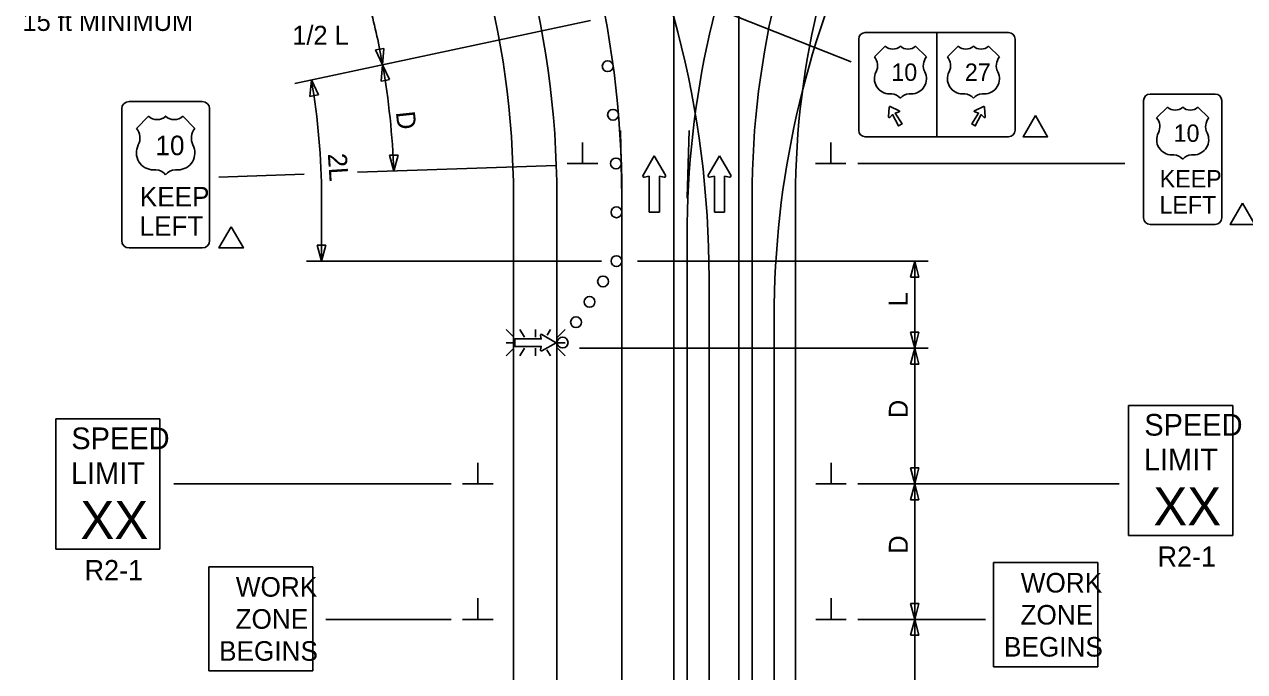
# Model space of a CAD drawing. Extents: x 16440 to 18464, y 5737 to 6974.
# Drawn here: x 16741.1 to 17191.2, y 6394.6 to 6633.2 of the extents above; entities that cross this region are included whole.
import ezdxf

# ---------------------------------------------------------------- set-up
doc = ezdxf.new("R2010")
doc.units = 0
for name, color, linetype in [('ALI_LEGAL_EX', 7, 'Continuous'), ('MT_SCRATCH_LEVEL_E', 7, 'Continuous'), ('PAVT_EDGE_EX', 7, 'Continuous'), ('TRAFFIC_SIGNS_PR', 7, 'Continuous'), ('TYPICAL_EX', 7, 'Continuous'), ('TYPICAL_TEXT_DIMEN_PR', 7, 'Continuous')]:
    doc.layers.add(name, color=color, linetype=linetype)

msp = doc.modelspace()

# ---------------------------------------------------------------- linework, layer by layer
at = {"layer": 'ALI_LEGAL_EX'}
for p, q in [((16980.68, 6974.12), (16980.68, 6155.98)), ((17004.68, 6974.12), (17004.68, 6155.98)), ((16980.68, 6891.53), (16980.68, 6027.61)), ((17004.68, 6891.53), (17004.68, 6027.61)), ((16961.51, 6069.17), (16961.51, 6569.52)), ((16985.51, 6054.68), (16985.51, 6555.03)), ((16993.65, 6039.29), (16993.65, 6539.64)), ((17017.65, 6024.8), (17017.65, 6525.15))]:
    msp.add_line(p, q, dxfattribs=at)
for points in [[(16961.46, 6569.17), (16961.51, 6569.52), (16960.94, 6594.16)], [(16985.56, 6569.17), (16985.51, 6569.52), (16986.34, 6594.15)], [(16961.51, 6469.17), (16961.51, 6494.17)], [(16985.51, 6469.17), (16985.51, 6494.17)]]:
    msp.add_lwpolyline(points, dxfattribs=at)
for centre, radius, start, end in [((16597.51, 6569.52), 364, 0, 57.2958), ((16629.65, 6539.64), 364, 0, 57.2958), ((17325.51, 6555.03), 340, 129.5666, 180), ((17357.65, 6525.15), 340, 129.5666, 180)]:
    msp.add_arc(centre, radius, start, end, dxfattribs=at)
at = {"layer": 'MT_SCRATCH_LEVEL_E'}
for p, q in [((16973.43, 6584.82), (16969.32, 6577.59)), ((16977.58, 6577.59), (16973.43, 6584.82)), ((16997.48, 6584.82), (16993.37, 6577.59)), ((17001.63, 6577.59), (16997.48, 6584.82)), ((16969.8, 6576.9), (16971.58, 6577.22)), ((16971.58, 6577.22), (16971.58, 6563.96)), ((16975.32, 6563.96), (16975.32, 6577.22)), ((16975.32, 6577.22), (16977.1, 6576.9)), ((16993.85, 6576.9), (16995.63, 6577.22)), ((16995.63, 6577.22), (16995.63, 6563.96)), ((16999.37, 6563.96), (16999.37, 6577.22)), ((16999.37, 6577.22), (17001.15, 6576.9)), ((16971.58, 6563.96), (16975.32, 6563.96)), ((16995.63, 6563.96), (16999.37, 6563.96))]:
    msp.add_line(p, q, dxfattribs=at)
for centre, start, end in [((16969.73, 6577.36), 150.4248, 279.9638), ((16977.17, 6577.36), 260.0362, 29.7731), ((16993.78, 6577.36), 150.4248, 279.9638), ((17001.22, 6577.36), 260.0362, 29.7731)]:
    msp.add_arc(centre, 0.463, start, end, dxfattribs=at)
at = {"layer": 'PAVT_EDGE_EX'}
for p, q in [((16921.51, 6569.52), (16921.51, 6043.9)), ((16937.51, 6569.52), (16937.51, 6043.9)), ((17009.51, 6569.52), (17009.51, 6043.9)), ((17025.51, 6569.52), (17025.51, 6043.9))]:
    msp.add_line(p, q, dxfattribs=at)
for centre, radius, start, end in [((16597.51, 6569.52), 340, 0, 62.1564), ((16597.51, 6569.52), 324, 0, 62.1564), ((17325.51, 6569.52), 316, 123.7854, 180), ((17325.51, 6569.52), 300, 123.7854, 180), ((17325.51, 6569.52), 300, 180, 180.00000277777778)]:
    msp.add_arc(centre, radius, start, end, dxfattribs=at)
at = {"layer": 'TRAFFIC_SIGNS_PR'}
for p, q in [((17051.26, 6630.24), (17104.13, 6630.24)), ((17077.7, 6630.24), (17077.7, 6591.79)), ((17048.86, 6627.84), (17048.86, 6594.19)), ((17106.53, 6627.84), (17106.53, 6594.19)), ((17180.37, 6607.57), (17156.34, 6607.57)), ((16806.71, 6604.81), (16779.71, 6604.81)), ((17059.85, 6599.15), (17060.14, 6602.78)), ((17060.51, 6602.99), (17063.79, 6601.42)), ((17094.88, 6602.99), (17091.6, 6601.42)), ((17095.54, 6599.15), (17095.25, 6602.78)), ((17153.94, 6605.16), (17153.94, 6561.91)), ((17182.77, 6561.91), (17182.77, 6605.16)), ((16777.01, 6602.11), (16777.01, 6553.51)), ((16809.41, 6553.51), (16809.41, 6602.11)), ((17051.26, 6591.79), (17104.13, 6591.79)), ((17156.34, 6559.51), (17180.37, 6559.51)), ((16779.71, 6550.81), (16806.71, 6550.81)), ((16921.58, 6517.92), (16918.76, 6520.74)), ((16923.88, 6520.74), (16925.51, 6517.92)), ((16929.67, 6517.92), (16929.67, 6520.74)), ((16935.13, 6520.74), (16933.93, 6518.65)), ((16940.57, 6520.74), (16937.75, 6517.92)), ((16921.58, 6515.89), (16918.76, 6515.89)), ((16921.58, 6513.86), (16918.76, 6511.04)), ((16925.53, 6513.86), (16923.9, 6511.04)), ((16929.67, 6513.86), (16929.67, 6511.04)), ((16933.85, 6513.23), (16935.11, 6511.04)), ((16937.75, 6515.89), (16940.57, 6515.89)), ((16940.57, 6511.04), (16937.75, 6513.86)), ((17148.4, 6492.75), (17186.8, 6492.75)), ((17148.4, 6444.75), (17148.4, 6492.75)), ((17186.8, 6444.75), (17186.8, 6492.75)), ((16752.64, 6487.76), (16791.04, 6487.76)), ((16752.64, 6439.76), (16752.64, 6487.76)), ((16791.04, 6439.76), (16791.04, 6487.76)), ((17148.4, 6444.75), (17186.8, 6444.75)), ((16752.64, 6439.76), (16791.04, 6439.76)), ((16809.1, 6394.86), (16809.1, 6433.26)), ((16809.1, 6433.26), (16847.5, 6433.26)), ((16847.5, 6394.86), (16847.5, 6433.26)), ((17098.62, 6396.4), (17098.62, 6434.8)), ((17098.62, 6434.8), (17137.02, 6434.8)), ((17137.02, 6396.4), (17137.02, 6434.8)), ((17098.62, 6396.4), (17137.02, 6396.4)), ((16809.1, 6394.86), (16847.5, 6394.86))]:
    msp.add_line(p, q, dxfattribs=at)
for points in [[(17063.75, 6600.94), (17062.34, 6600.55), (17064.86, 6596.56), (17063.53, 6595.8), (17061.33, 6599.97), (17060.29, 6598.94)], [(17091.64, 6600.94), (17093.05, 6600.55), (17090.53, 6596.56), (17091.86, 6595.8), (17094.06, 6599.97), (17095.1, 6598.94)], [(16931.49, 6518.57), (16931.72, 6517.28), (16922, 6517.28), (16922, 6514.53), (16931.72, 6514.53), (16931.49, 6513.23)], [(16931.99, 6512.88), (16937.3, 6515.89), (16931.99, 6518.93)]]:
    msp.add_lwpolyline(points, dxfattribs=at)
for centre in [(16956.26, 6617.81), (16958.22, 6599.92), (16959.28, 6581.96), (16959.5, 6563.96), (16959.5, 6545.96), (16959.5, 6545.96), (16954.53, 6538.45), (16949.56, 6530.94), (16944.59, 6523.44), (16939.62, 6515.93)]:
    msp.add_circle(centre, 2, dxfattribs=at)
for centre, radius, start, end in [((17051.26, 6627.84), 2.4, 90, 180), ((17051.26, 6627.84), 2.4, 90, 180), ((17104.13, 6627.84), 2.4, 0, 90), ((17156.34, 6605.16), 2.4, 90, 180), ((17180.37, 6605.16), 2.4, 0, 90), ((16779.71, 6602.1), 2.7, 90, 180), ((16806.71, 6602.1), 2.7, 0, 90), ((17060.4, 6602.76), 0.261, 64.4823, 175.5177), ((17094.99, 6602.76), 0.261, 4.4823, 115.5177), ((17060.11, 6599.13), 0.261, 175.5177, 314.0115), ((17063.68, 6601.19), 0.261, 285.9885, 64.4823), ((17091.71, 6601.19), 0.261, 115.5177, 254.0115), ((17095.28, 6599.13), 0.261, 225.9885, 4.4823), ((17051.26, 6594.19), 2.4, 180, 270), ((17104.13, 6594.19), 2.4, 270, 0), ((17156.34, 6561.91), 2.4, 180, 270), ((17180.37, 6561.91), 2.4, 270, 0), ((16779.71, 6553.5), 2.7, 180, 270), ((16806.71, 6553.5), 2.7, 270, 0), ((16931.83, 6518.63), 0.341, 61.4833, 189.9593), ((16931.83, 6513.18), 0.341, 170.7308, 298.8916)]:
    msp.add_arc(centre, radius, start, end, dxfattribs=at)
at = {"layer": 'TYPICAL_EX'}
for p, q in [((17054.62, 6621.23), (17058.62, 6625.23)), ((17073.84, 6621.23), (17069.84, 6625.23)), ((17081.55, 6621.23), (17085.55, 6625.23)), ((17100.77, 6621.23), (17096.77, 6625.23)), ((17060.22, 6607.6), (17061.02, 6607.6)), ((17068.24, 6607.6), (17067.44, 6607.6)), ((17087.15, 6607.6), (17087.95, 6607.6)), ((17095.17, 6607.6), (17094.37, 6607.6)), ((17158.74, 6598.76), (17162.75, 6602.76)), ((17177.97, 6598.76), (17173.96, 6602.76)), ((16782.41, 6594.91), (16786.91, 6599.41)), ((16804.01, 6594.91), (16799.51, 6599.41)), ((17164.34, 6585.13), (17165.14, 6585.13)), ((17172.36, 6585.13), (17171.56, 6585.13)), ((16788.7, 6579.59), (16789.6, 6579.59)), ((16797.71, 6579.59), (16796.81, 6579.59))]:
    msp.add_line(p, q, dxfattribs=at)
for centre, radius, start, end in [((17061.43, 6628.15), 4.05, 226.1404, 313.8596), ((17067.03, 6628.15), 4.05, 226.1404, 313.8596), ((17088.36, 6628.15), 4.05, 226.1404, 313.8596), ((17093.96, 6628.15), 4.05, 226.1404, 313.8596), ((17050.82, 6618.02), 4.97, 333.0977, 40.1936), ((17077.64, 6618.02), 4.97, 139.8064, 206.9023), ((17077.75, 6618.02), 4.97, 333.0977, 40.1936), ((17104.57, 6618.02), 4.97, 139.8064, 206.9023), ((17060.23, 6613.2), 5.6, 152.6698, 269.9013), ((17068.23, 6613.2), 5.6, 270.0987, 27.3302), ((17087.16, 6613.2), 5.6, 152.6698, 269.9013), ((17095.16, 6613.2), 5.6, 270.0987, 27.3302), ((17061.03, 6603.59), 4.01, 37.1038, 90.1385), ((17067.43, 6603.59), 4.01, 89.8615, 142.8962), ((17087.96, 6603.59), 4.01, 37.1038, 90.1385), ((17094.36, 6603.59), 4.01, 89.8615, 142.8962), ((17165.55, 6605.68), 4.05, 226.1404, 313.8596), ((17171.16, 6605.68), 4.05, 226.1404, 313.8596), ((16790.06, 6602.68), 4.55, 226.1404, 313.8596), ((16796.36, 6602.68), 4.55, 226.1404, 313.8596), ((17154.95, 6595.55), 4.97, 333.0977, 40.1936), ((17181.76, 6595.55), 4.97, 139.8064, 206.9023), ((16778.14, 6591.3), 5.58, 333.0977, 40.1936), ((16808.27, 6591.3), 5.58, 139.8064, 206.9023), ((17164.35, 6590.73), 5.6, 152.6698, 269.9013), ((17172.35, 6590.73), 5.6, 270.0987, 27.3302), ((16788.71, 6585.89), 6.29, 152.6698, 269.9013), ((16797.7, 6585.89), 6.29, 270.0987, 27.3302), ((17165.15, 6581.11), 4.01, 37.1038, 90.1385), ((17171.55, 6581.11), 4.01, 89.8615, 142.8962), ((16789.61, 6575.09), 4.51, 37.1038, 90.1385), ((16796.8, 6575.09), 4.51, 89.8615, 142.8962)]:
    msp.add_arc(centre, radius, start, end, dxfattribs=at)
at = {"layer": 'TYPICAL_TEXT_DIMEN_PR'}
for p, q in [((16964.45, 6651.69), (17046.11, 6619.48)), ((16840.84, 6611.45), (16949.94, 6634.73)), ((16870.65, 6623.86), (16872.19, 6624.13)), ((16873.22, 6618.36), (16870.65, 6623.86)), ((16872.19, 6624.13), (16873.74, 6624.4)), ((16873.74, 6624.4), (16873.22, 6618.36)), ((16872.69, 6612.31), (16873.22, 6618.36)), ((16873.22, 6618.36), (16875.79, 6612.86)), ((16846.44, 6606.71), (16846.97, 6612.76)), ((16846.97, 6612.76), (16849.54, 6607.26)), ((16874.24, 6612.59), (16872.69, 6612.31)), ((16875.79, 6612.86), (16874.24, 6612.59)), ((16849.54, 6607.26), (16847.99, 6606.98)), ((16847.99, 6606.98), (16846.44, 6606.71)), ((16946.99, 6581.91), (16946.99, 6589.7)), ((17038.53, 6581.91), (17038.53, 6589.7)), ((16877.34, 6579.16), (16875.77, 6585.02)), ((16875.77, 6585.02), (16877.34, 6585.02)), ((16877.34, 6585.02), (16878.91, 6585.02)), ((16878.91, 6585.02), (16877.34, 6579.16)), ((16863.93, 6578.7), (16937.31, 6581.22)), ((16952.61, 6581.91), (16941.36, 6581.91)), ((17044.15, 6581.91), (17032.9, 6581.91)), ((17048.51, 6581.91), (17146.98, 6581.91)), ((16812.87, 6576.94), (16844.31, 6578.02)), ((16850.69, 6569.52), (16850.69, 6545.96)), ((16850.69, 6545.96), (16849.12, 6551.82)), ((16849.12, 6551.82), (16850.69, 6551.82)), ((16850.69, 6551.82), (16852.26, 6551.82)), ((16852.26, 6551.82), (16850.69, 6545.96)), ((16954.01, 6545.96), (16845.14, 6545.96)), ((16967.28, 6545.96), (17074.51, 6545.96)), ((17067.94, 6540.1), (17069.51, 6545.96)), ((17069.51, 6545.96), (17069.51, 6513.85)), ((17069.51, 6545.96), (17071.08, 6540.1)), ((17069.51, 6540.1), (17067.94, 6540.1)), ((17071.08, 6540.1), (17069.51, 6540.1)), ((17069.51, 6513.85), (17067.94, 6519.72)), ((17067.94, 6519.72), (17069.51, 6519.72)), ((17069.51, 6519.72), (17071.08, 6519.72)), ((17071.08, 6519.72), (17069.51, 6513.85)), ((16945.91, 6513.85), (17074.51, 6513.85)), ((17067.94, 6507.99), (17069.51, 6513.85)), ((17069.51, 6513.85), (17069.51, 6463.85)), ((17069.51, 6513.85), (17071.08, 6507.99)), ((17069.51, 6507.99), (17067.94, 6507.99)), ((17071.08, 6507.99), (17069.51, 6507.99)), ((16908.39, 6463.85), (16908.39, 6471.64)), ((17038.64, 6463.85), (17038.64, 6471.64)), ((17069.51, 6463.85), (17067.94, 6469.72)), ((17067.94, 6469.72), (17069.51, 6469.72)), ((17069.51, 6469.72), (17071.08, 6469.72)), ((17071.08, 6469.72), (17069.51, 6463.85)), ((16796.27, 6463.85), (16898.51, 6463.85)), ((16902.76, 6463.85), (16914.01, 6463.85)), ((17044.26, 6463.85), (17033.01, 6463.85)), ((17048.51, 6463.85), (17144.95, 6463.85)), ((17067.94, 6457.99), (17069.51, 6463.85)), ((17069.51, 6463.85), (17069.51, 6413.85)), ((17069.51, 6463.85), (17071.08, 6457.99)), ((17069.51, 6457.99), (17067.94, 6457.99)), ((17071.08, 6457.99), (17069.51, 6457.99)), ((16908.39, 6413.85), (16908.39, 6421.64)), ((17038.64, 6413.85), (17038.64, 6421.64)), ((17069.51, 6413.85), (17067.94, 6419.72)), ((17067.94, 6419.72), (17069.51, 6419.72)), ((17069.51, 6419.72), (17071.08, 6419.72)), ((17071.08, 6419.72), (17069.51, 6413.85)), ((16898.51, 6413.85), (16852.31, 6413.85)), ((16902.76, 6413.85), (16914.01, 6413.85)), ((17044.26, 6413.85), (17033.01, 6413.85)), ((17048.51, 6413.85), (17095.59, 6413.85)), ((17067.94, 6407.99), (17069.51, 6413.85)), ((17069.51, 6413.85), (17069.51, 6363.85)), ((17069.51, 6413.85), (17071.08, 6407.99)), ((17069.51, 6407.99), (17067.94, 6407.99)), ((17071.08, 6407.99), (17069.51, 6407.99))]:
    msp.add_line(p, q, dxfattribs=at)
for points in [[(17114.01, 6599.66), (17109.48, 6591.83), (17118.53, 6591.83)], [(17190.44, 6567.27), (17185.92, 6559.44), (17194.97, 6559.44)], [(16817.37, 6558.64), (16812.84, 6550.81), (16821.89, 6550.81)]]:
    msp.add_lwpolyline(points, close=True, dxfattribs=at)
for radius, start, end in [(280, 10.0461, 14.4629), (280, 1.9734, 10.046), (253.18, 0, 9.834)]:
    msp.add_arc((16597.51, 6569.52), radius, start, end, dxfattribs=at)

# ---------------------------------------------------------------- texts
at = {"layer": 'TRAFFIC_SIGNS_PR'}
for s, height, p in [('10', 6.408, (17060.89, 6612.42)), ('27', 6.408, (17087.99, 6612.42)), ('10', 6.408, (17165.01, 6589.94)), ('10', 7.2, (16789.45, 6585.01)), ('KEEP', 6.408, (17159.88, 6573.12)), ('KEEP', 7.2, (16783.69, 6566.11)), ('LEFT', 6.408, (17159.79, 6563.51)), ('LEFT', 7.2, (16783.59, 6555.31)), ('SPEED', 8, (17154.17, 6481.61)), ('SPEED', 8, (16758.4, 6476.62)), ('LIMIT', 8, (17154.01, 6468.82)), ('LIMIT', 8, (16758.24, 6463.82)), ('XX', 14.031, (17157.52, 6448.51)), ('XX', 14.031, (16761.75, 6443.51)), ('R2-1', 7.44, (17159.08, 6433.31)), ('R2-1', 7.44, (16763.31, 6428.32)), ('WORK', 7.217, (16819.1, 6422.23)), ('WORK', 7.217, (17108.62, 6423.77)), ('ZONE', 7.217, (17108.51, 6411.96)), ('ZONE', 7.217, (16818.98, 6410.42)), ('BEGINS', 7.217, (16812.91, 6398.61)), ('BEGINS', 7.217, (17102.43, 6400.15))]:
    msp.add_text(s, height=height, dxfattribs=at).set_placement(p)
at = {"layer": 'TYPICAL_TEXT_DIMEN_PR'}
for s, p in [('15 ft MINIMUM', (16740.39, 6630.83)), ('1/2 L', (16839.91, 6625.71))]:
    msp.add_text(s, height=7, dxfattribs=at).set_placement(p)
for s, rotation, p in [('D', 276.0098, (16878.11, 6600.89)), ('2L', 273.8016, (16853.01, 6585.51)), ('L', 90, (17066.95, 6529.26)), ('D', 90, (17066.95, 6488.07)), ('D', 90, (17066.95, 6438.07))]:
    msp.add_text(s, height=7, rotation=rotation, dxfattribs=at).set_placement(p)

doc.saveas('drawing.dxf')
